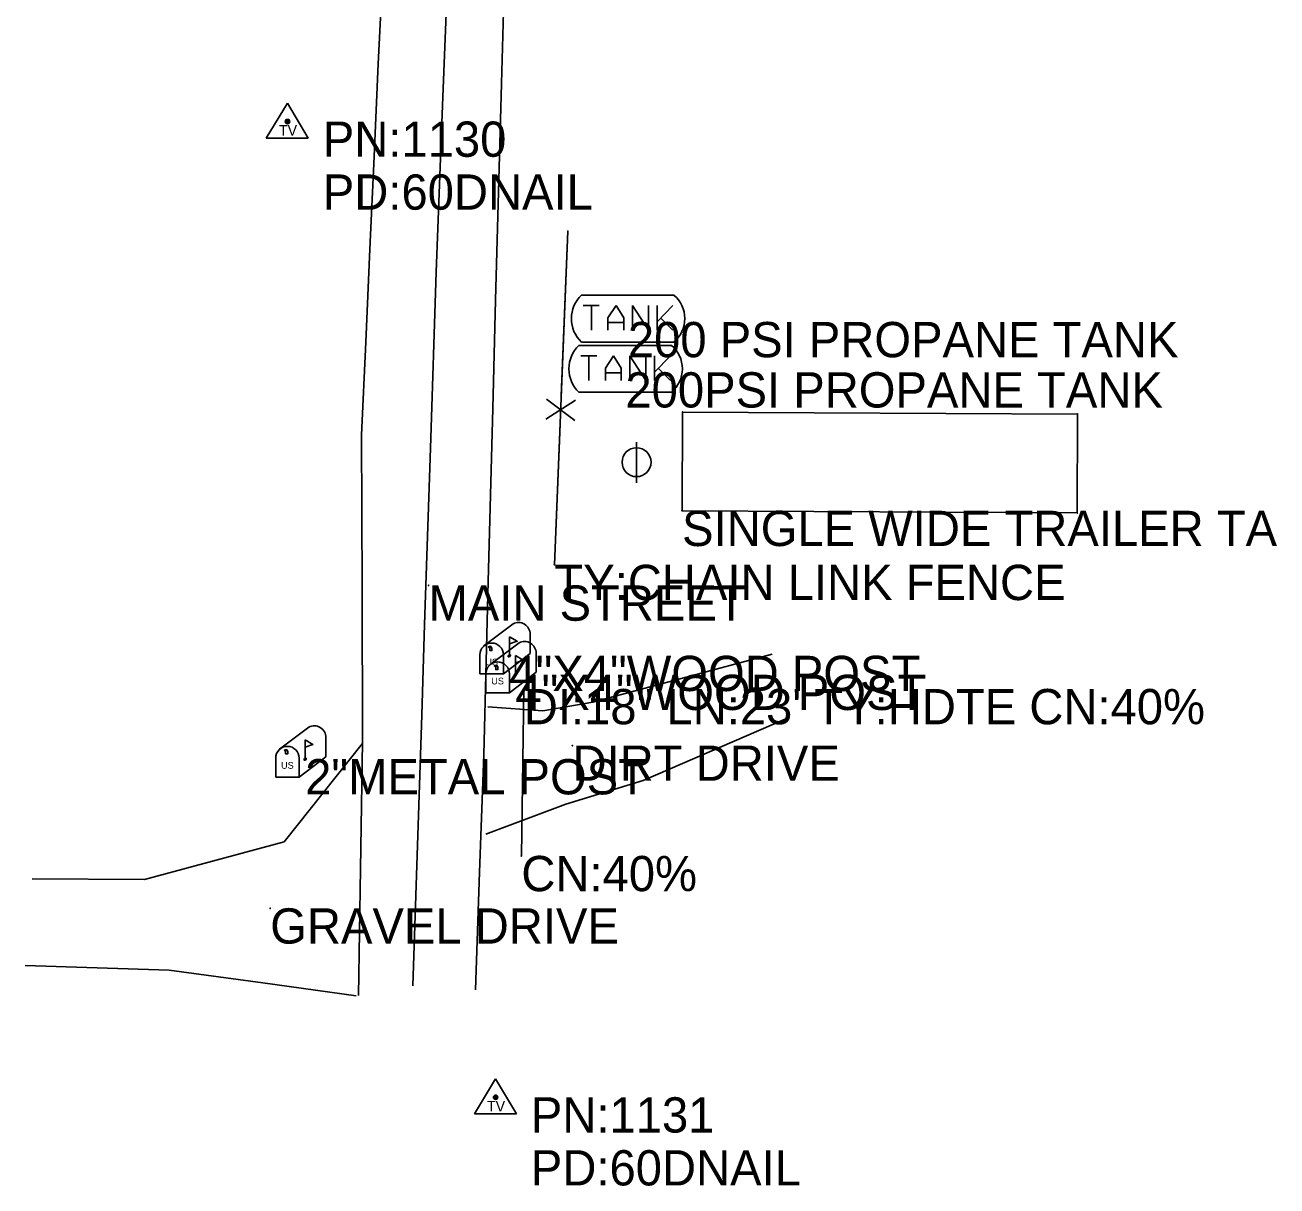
# Model space of a CAD drawing. Extents: x 1050807 to 1053552, y 395828 to 398415.
# Drawn here: x 1051564.3 to 1051741.7, y 397762.6 to 397927.2 of the extents above; entities that cross this region are included whole.
import ezdxf

# ---------------------------------------------------------------- set-up
doc = ezdxf.new("R2010")
doc.units = 0
for name, color, linetype in [('S_BUILDING', 7, 'Continuous'), ('S_BUILDING_ANNOT', 7, 'Continuous'), ('S_CROSS_DRAIN', 7, 'Continuous'), ('S_CROSS_DRAIN_ANNOT', 7, 'Continuous'), ('S_DRG_PT_SYM', 7, 'Continuous'), ('S_DRIVEWAY', 7, 'Continuous'), ('S_EDGE_PAVEMENT', 7, 'Continuous'), ('S_FENCE', 7, 'Continuous'), ('S_FENCE_ANNOT', 7, 'Continuous'), ('S_MAILBOX', 7, 'Continuous'), ('S_MAILBOX_ANNOT', 7, 'Continuous'), ('S_MSC_PT_SYM', 7, 'Continuous'), ('S_PAVEMENT_CROWN', 7, 'Continuous'), ('S_SECONDARY_CTL', 7, 'Continuous'), ('S_SECONDARY_CTL_ANNOT', 7, 'Continuous'), ('S_STR_PT_SYM', 7, 'Continuous'), ('S_SURVEY_TEXT_ANNOT', 7, 'Continuous'), ('S_TANK', 7, 'Continuous'), ('S_TANK_ANNOT', 7, 'Continuous'), ('S_UTILITY_POLE', 7, 'Continuous')]:
    doc.layers.add(name, color=color, linetype=linetype)

msp = doc.modelspace()

# ---------------------------------------------------------------- linework, layer by layer
at = {"layer": 'S_BUILDING'}
for p, q in [((1051657.45, 397872.37), (1051657.38, 397858.37)), ((1051657.45, 397872.3), (1051657.38, 397858.37)), ((1051713.45, 397872.09), (1051657.45, 397872.37)), ((1051713.38, 397858.08), (1051713.45, 397872.09)), ((1051657.38, 397858.37), (1051713.38, 397858.08))]:
    msp.add_line(p, q, dxfattribs=at)
at = {"layer": 'S_CROSS_DRAIN'}
msp.add_line((1051634.95, 397833.1), (1051634.6, 397809.43), dxfattribs=at)
at = {"layer": 'S_DRG_PT_SYM'}
for points in [[(1051634.95, 397833.1), (1051634.95, 397833.15), (1051634.95, 397833.1), (1051634.9, 397833.1), (1051634.95, 397833.1), (1051634.95, 397833.05), (1051634.95, 397833.1), (1051635, 397833.1)], [(1051634.6, 397809.43), (1051634.6, 397809.48), (1051634.6, 397809.43), (1051634.55, 397809.43), (1051634.6, 397809.43), (1051634.6, 397809.38), (1051634.6, 397809.43), (1051634.65, 397809.43)]]:
    msp.add_lwpolyline(points, dxfattribs=at)
at = {"layer": 'S_DRIVEWAY'}
for points in [[(1051629.87, 397830.57), (1051637.64, 397829.99), (1051644.75, 397831.22), (1051657.46, 397834.62), (1051670.16, 397838.02)], [(1051672.07, 397828.87), (1051651.85, 397820.14), (1051640.92, 397816.77), (1051629.57, 397812.51)], [(1051612.02, 397825.32), (1051600.97, 397811.45), (1051581.21, 397806.07), (1051565.29, 397806.19)], [(1051564.26, 397793.91), (1051584.69, 397793.24), (1051597.94, 397791.42), (1051611.2, 397789.59)]]:
    msp.add_lwpolyline(points, dxfattribs=at)
at = {"layer": 'S_EDGE_PAVEMENT'}
for points in [[(1051602.35, 398068.65), (1051612.02, 398062.41), (1051615.42, 398052.6), (1051616.64, 398028.83), (1051617.09, 398007), (1051617.53, 397985.17), (1051616.73, 397969.32), (1051615.92, 397953.47), (1051615.11, 397937.61), (1051614.31, 397921.76), (1051613.72, 397908.61), (1051613.14, 397895.46), (1051612.55, 397882.3), (1051611.96, 397869.15), (1051612.02, 397847.38), (1051612.07, 397825.61), (1051611.81, 397807.62), (1051611.54, 397789.62)], [(1051647.36, 398067.62), (1051642.01, 398064.42), (1051639.06, 398057.05), (1051637.93, 398043.3), (1051636.8, 398029.54), (1051635.43, 398006.82), (1051634.07, 397984.09), (1051633.15, 397959.21), (1051632.23, 397934.32), (1051631.81, 397918.96), (1051631.38, 397903.6), (1051630.96, 397888.24), (1051630.54, 397872.88), (1051629.92, 397848.36), (1051629.3, 397823.83), (1051628.69, 397807.15), (1051628.08, 397790.46)]]:
    msp.add_lwpolyline(points, dxfattribs=at)
at = {"layer": 'S_FENCE'}
for p, q in [((1051639.29, 397850.71), (1051641.2, 397898)), ((1051638.07, 397871.34), (1051642.28, 397874.04)), ((1051638.07, 397871.34), (1051642.28, 397874.04)), ((1051642.16, 397871.18), (1051638.19, 397874.21)), ((1051642.16, 397871.18), (1051638.19, 397874.21))]:
    msp.add_line(p, q, dxfattribs=at)
for points in [[(1051640.26, 397874.69), (1051641.2, 397898)], [(1051640.26, 397874.69), (1051641.2, 397898)], [(1051639.29, 397850.71), (1051640.1, 397870.7)], [(1051639.29, 397850.71), (1051640.1, 397870.7)]]:
    msp.add_lwpolyline(points, dxfattribs=at)
at = {"layer": 'S_MAILBOX'}
for p, q in [((1051629.29, 397839.23), (1051633.42, 397842.34)), ((1051635.85, 397840.87), (1051635.85, 397838.15)), ((1051630.13, 397836.55), (1051634.27, 397839.65)), ((1051632.9, 397840.52), (1051632.9, 397837.81)), ((1051628.73, 397837.96), (1051628.73, 397835.24)), ((1051632.06, 397835.24), (1051635.85, 397838.15)), ((1051632.06, 397837.96), (1051632.06, 397835.24)), ((1051633.75, 397837.83), (1051633.75, 397835.12)), ((1051636.7, 397838.18), (1051636.7, 397835.47)), ((1051628.73, 397835.24), (1051632.06, 397835.24)), ((1051629.58, 397835.27), (1051629.58, 397832.56)), ((1051632.9, 397832.56), (1051636.7, 397835.47)), ((1051632.9, 397835.27), (1051632.9, 397832.56)), ((1051629.58, 397832.56), (1051632.9, 397832.56)), ((1051600.34, 397824.58), (1051604.48, 397827.69)), ((1051603.96, 397825.87), (1051603.96, 397823.16)), ((1051606.91, 397826.22), (1051606.91, 397823.5)), ((1051599.79, 397823.31), (1051599.79, 397820.59)), ((1051603.11, 397820.59), (1051606.91, 397823.5)), ((1051603.11, 397823.31), (1051603.11, 397820.59)), ((1051599.79, 397820.59), (1051603.11, 397820.59))]:
    msp.add_line(p, q, dxfattribs=at)
for points in [[(1051629.92, 397839.08), (1051630.14, 397838.94), (1051630.14, 397838.55), (1051630.44, 397838.55), (1051630.44, 397838.91), (1051630.25, 397839.16), (1051629.92, 397839.1)], [(1051632.9, 397840.52), (1051634.01, 397839.86), (1051632.9, 397839.51)], [(1051633.75, 397837.83), (1051634.85, 397837.17), (1051633.75, 397836.82)], [(1051630.76, 397836.39), (1051630.98, 397836.25), (1051630.98, 397835.86), (1051631.29, 397835.86), (1051631.29, 397836.22), (1051631.09, 397836.47), (1051630.76, 397836.41)], [(1051603.96, 397825.87), (1051605.07, 397825.21), (1051603.96, 397824.86)], [(1051600.97, 397824.42), (1051601.19, 397824.29), (1051601.19, 397823.9), (1051601.5, 397823.9), (1051601.5, 397824.26), (1051601.31, 397824.51), (1051600.97, 397824.45)]]:
    msp.add_lwpolyline(points, dxfattribs=at)
for centre, end in [((1051634.19, 397840.87), 117.5718), ((1051630.4, 397837.96), 180), ((1051635.04, 397838.18), 117.5718), ((1051631.24, 397835.27), 180), ((1051605.25, 397826.22), 117.5718), ((1051601.45, 397823.31), 180)]:
    msp.add_arc(centre, 1.66, 0, end, dxfattribs=at)
for centre in [(1051632.9, 397837.81), (1051633.75, 397835.12), (1051603.96, 397823.16)]:
    msp.add_ellipse(centre, major_axis=(0.145, 0.132), ratio=0.564646, dxfattribs=at)
at = {"layer": 'S_MSC_PT_SYM'}
for points in [[(1051641.2, 397898), (1051641.2, 397898.05), (1051641.2, 397898), (1051641.15, 397898), (1051641.2, 397898), (1051641.2, 397897.95), (1051641.2, 397898), (1051641.25, 397898)], [(1051639.29, 397850.71), (1051639.29, 397850.76), (1051639.29, 397850.71), (1051639.24, 397850.71), (1051639.29, 397850.71), (1051639.29, 397850.66), (1051639.29, 397850.71), (1051639.34, 397850.71)], [(1051621.45, 397847.78), (1051621.45, 397847.83), (1051621.45, 397847.78), (1051621.4, 397847.78), (1051621.45, 397847.78), (1051621.45, 397847.73), (1051621.45, 397847.78), (1051621.5, 397847.78)], [(1051641.85, 397825.08), (1051641.85, 397825.13), (1051641.85, 397825.08), (1051641.8, 397825.08), (1051641.85, 397825.08), (1051641.85, 397825.03), (1051641.85, 397825.08), (1051641.9, 397825.08)], [(1051599.01, 397802), (1051599.01, 397802.05), (1051599.01, 397802), (1051598.96, 397802), (1051599.01, 397802), (1051599.01, 397801.95), (1051599.01, 397802), (1051599.06, 397802)]]:
    msp.add_lwpolyline(points, dxfattribs=at)
at = {"layer": 'S_PAVEMENT_CROWN'}
msp.add_lwpolyline([(1051619.24, 397791.01), (1051619.65, 397803.82), (1051620.06, 397816.63), (1051620.48, 397829.45), (1051620.89, 397842.26), (1051621.71, 397867.23), (1051622.53, 397892.19), (1051623.49, 397917.08), (1051624.46, 397941.96), (1051625.3, 397963.26), (1051626.14, 397984.55), (1051626.74, 398009.08), (1051627.35, 398033.62), (1051627.62, 398048.39), (1051627.88, 398063.17)], dxfattribs=at)
at = {"layer": 'S_SECONDARY_CTL'}
for p, q in [((1051601.46, 397916.17), (1051598.45, 397911.21)), ((1051601.46, 397916.17), (1051604.41, 397911.21)), ((1051598.45, 397911.21), (1051604.41, 397911.21)), ((1051630.95, 397777.82), (1051627.94, 397772.86)), ((1051630.95, 397777.82), (1051633.9, 397772.86)), ((1051627.94, 397772.86), (1051633.9, 397772.86))]:
    msp.add_line(p, q, dxfattribs=at)
for centre, radius in [((1051601.46, 397913.56), 0.311), ((1051601.46, 397913.56), 0.183), ((1051601.46, 397913.56), 0.103), ((1051630.95, 397775.21), 0.311), ((1051630.95, 397775.21), 0.183), ((1051630.95, 397775.21), 0.103)]:
    msp.add_circle(centre, radius, dxfattribs=at)
at = {"layer": 'S_STR_PT_SYM'}
for points in [[(1051657.45, 397872.37), (1051657.45, 397872.42), (1051657.45, 397872.37), (1051657.4, 397872.37), (1051657.45, 397872.37), (1051657.45, 397872.32), (1051657.45, 397872.37), (1051657.5, 397872.37)], [(1051657.45, 397872.3), (1051657.45, 397872.35), (1051657.45, 397872.3), (1051657.4, 397872.3), (1051657.45, 397872.3), (1051657.45, 397872.25), (1051657.45, 397872.3), (1051657.5, 397872.3)], [(1051713.45, 397872.09), (1051713.45, 397872.14), (1051713.45, 397872.09), (1051713.4, 397872.09), (1051713.45, 397872.09), (1051713.45, 397872.04), (1051713.45, 397872.09), (1051713.5, 397872.09)], [(1051657.38, 397858.37), (1051657.38, 397858.42), (1051657.38, 397858.37), (1051657.33, 397858.37), (1051657.38, 397858.37), (1051657.38, 397858.32), (1051657.38, 397858.37), (1051657.43, 397858.37)], [(1051657.38, 397858.37), (1051657.38, 397858.42), (1051657.38, 397858.37), (1051657.33, 397858.37), (1051657.38, 397858.37), (1051657.38, 397858.32), (1051657.38, 397858.37), (1051657.43, 397858.37)], [(1051713.38, 397858.08), (1051713.38, 397858.13), (1051713.38, 397858.08), (1051713.33, 397858.08), (1051713.38, 397858.08), (1051713.38, 397858.03), (1051713.38, 397858.08), (1051713.43, 397858.08)]]:
    msp.add_lwpolyline(points, dxfattribs=at)
at = {"layer": 'S_TANK'}
for p, q in [((1051643.11, 397888.95), (1051656.22, 397888.95)), ((1051643.37, 397887.46), (1051645.63, 397887.46)), ((1051644.53, 397887.46), (1051644.53, 397883.97)), ((1051646.86, 397885.72), (1051648.02, 397887.46)), ((1051648.02, 397887.46), (1051649.12, 397885.72)), ((1051650.34, 397883.97), (1051650.34, 397887.46)), ((1051650.34, 397887.46), (1051652.6, 397883.97)), ((1051652.6, 397883.97), (1051652.6, 397887.46)), ((1051653.83, 397887.46), (1051653.83, 397883.97)), ((1051653.83, 397885.14), (1051656.09, 397887.46)), ((1051646.86, 397883.97), (1051646.86, 397885.72)), ((1051649.12, 397885.07), (1051646.86, 397885.07)), ((1051649.12, 397885.72), (1051649.12, 397883.97)), ((1051654.41, 397885.65), (1051656.09, 397883.97)), ((1051642.76, 397881.82), (1051655.87, 397881.82)), ((1051643.11, 397882.3), (1051656.22, 397882.3)), ((1051643.02, 397880.34), (1051645.28, 397880.34)), ((1051644.18, 397880.34), (1051644.18, 397876.85)), ((1051646.51, 397878.59), (1051647.67, 397880.34)), ((1051647.67, 397880.34), (1051648.77, 397878.59)), ((1051649.99, 397876.85), (1051649.99, 397880.34)), ((1051649.99, 397880.34), (1051652.25, 397876.85)), ((1051652.25, 397876.85), (1051652.25, 397880.34)), ((1051653.48, 397880.34), (1051653.48, 397876.85)), ((1051653.48, 397878.01), (1051655.74, 397880.34)), ((1051646.51, 397876.85), (1051646.51, 397878.59)), ((1051648.77, 397877.95), (1051646.51, 397877.95)), ((1051648.77, 397878.59), (1051648.77, 397876.85)), ((1051654.06, 397878.53), (1051655.74, 397876.85)), ((1051642.76, 397875.17), (1051655.87, 397875.17))]:
    msp.add_line(p, q, dxfattribs=at)
for centre, radius, start, end in [((1051646.29, 397885.62), 4.6, 133.7339, 226.2661), ((1051653.43, 397885.62), 4.34, 309.9965, 50.0035), ((1051645.94, 397878.5), 4.6, 133.7339, 226.2661), ((1051653.08, 397878.5), 4.34, 309.9965, 50.0035)]:
    msp.add_arc(centre, radius, start, end, dxfattribs=at)
at = {"layer": 'S_UTILITY_POLE'}
msp.add_line((1051650.93, 397862.33), (1051650.93, 397868.12), dxfattribs=at)
msp.add_circle((1051650.93, 397865.26), 2.05, dxfattribs=at)

# ---------------------------------------------------------------- texts
at = {"layer": 'S_BUILDING_ANNOT'}
msp.add_text('SINGLE WIDE TRAILER TA', height=5, dxfattribs=at).set_placement((1051657.38, 397853.37))
at = {"layer": 'S_CROSS_DRAIN_ANNOT'}
for s, p in [('DI:18" LN:23\' TY:HDTE CN:40%', (1051634.95, 397828.1)), ('CN:40%', (1051634.6, 397804.43))]:
    msp.add_text(s, height=5, dxfattribs=at).set_placement(p)
at = {"layer": 'S_FENCE_ANNOT'}
msp.add_text('TY:CHAIN LINK FENCE', height=5, dxfattribs=at).set_placement((1051639.29, 397845.71))
at = {"layer": 'S_MAILBOX'}
for p in [(1051629.5, 397836.44), (1051630.34, 397833.75), (1051600.55, 397821.79)]:
    msp.add_text('US', height=0.96, dxfattribs=at).set_placement(p)
at = {"layer": 'S_MAILBOX_ANNOT'}
for s, p in [('4"X4"WOOD POST', (1051632.9, 397832.81)), ('4"X4"WOOD POST', (1051633.75, 397830.12)), ('2"METAL POST', (1051603.96, 397818.16))]:
    msp.add_text(s, height=5, dxfattribs=at).set_placement(p)
at = {"layer": 'S_SECONDARY_CTL'}
for p in [(1051600.25, 397911.55), (1051629.74, 397773.2)]:
    msp.add_text('TV', height=1.5, dxfattribs=at).set_placement(p)
at = {"layer": 'S_SECONDARY_CTL_ANNOT'}
for s, p in [('PN:1130', (1051606.46, 397908.56)), ('PD:60DNAIL', (1051606.46, 397901.06)), ('PN:1131', (1051635.95, 397770.21)), ('PD:60DNAIL', (1051635.95, 397762.71))]:
    msp.add_text(s, height=5, dxfattribs=at).set_placement(p)
at = {"layer": 'S_SURVEY_TEXT_ANNOT'}
for s, p in [('MAIN STREET', (1051621.45, 397842.78)), ('DIRT DRIVE', (1051641.85, 397820.08)), ('GRAVEL DRIVE', (1051599.01, 397797))]:
    msp.add_text(s, height=5, dxfattribs=at).set_placement(p)
at = {"layer": 'S_TANK_ANNOT'}
for s, p in [('200 PSI PROPANE TANK', (1051649.7, 397880.14)), ('200PSI PROPANE TANK', (1051649.35, 397873.01))]:
    msp.add_text(s, height=5, dxfattribs=at).set_placement(p)

doc.saveas('drawing.dxf')
